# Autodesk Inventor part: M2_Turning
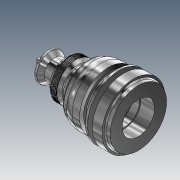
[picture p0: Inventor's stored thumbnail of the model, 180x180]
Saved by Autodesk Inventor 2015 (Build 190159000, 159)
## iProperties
Created: 2015-04
Part Number: M2_Turning
Material: Aço
Document SubType Name: Modeling
Designer: Andrew Almeida
Density: 7.85 g/cm^3
Appearance: Placa
Title: C:/Users/Andrew Almeida/Documents/Projeto WS2015/WS2015 CAD Data ANLAS/06/#06 - CNC Turning/01 - 3D Models/M2_Turning.stp
Creation Date: 2015-04-23
Sending System: Autodesk Translation Framework v4.0.0.5211
Preprocessor: ST-DEVELOPER v16.1
Author: Andrew Almeida
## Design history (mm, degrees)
node "M2_Turning1"
feature "Rosca1" dims "d0" = 10, "d1" = 0
feature "Rosca2" dims "d2" = 10, "d3" = 0
sketch "Esboço2"
  geometry: L1 (14.188, 0)-(14.188, 14.2); L2 (14.188, 14.2)-(13.447, 14.2); L3 (13.447, 14.2)-(13.447, 0); L4 (13.447, 0)-(14.188, 0); L5 (0, -49.8)-(0, 118.2) reference
  constraints: 8 end point
revolve "Revolução1" sketch "Esboço2" stored, may be unused: angle "d13" = 0 deg
sketch "Esboço1"
  geometry: L1 (-0.583, -0.051)-(-0.5, -0.051); L2 (0.083, -0.691)-(0, -0.851); L3 (-1, -0.851)-(-1.083, -0.691); L4 (-0.417, -0.051)-(-0.5, 0.109); L5 (-0.5, 0.109)-(-0.583, -0.051); L6 (-1, -0.851)-(-0.917, -0.691); L7 (-0.417, -0.051)-(-0.083, -0.691); L8 (-1.083, -0.691)-(-0.917, -0.691); L9 (0.083, -0.691)-(-0.083, -0.691); L10 (-1, -0.851)-(-1, -0.691); L11 (0, -0.851)-(0, -0.691); L12 (-0.5, 0.109)-(-0.5, 0); L13 (-1, -0.742)-(0, -0.742); L14 (-0.083, -0.691)-(0, -0.851); L15 (-0.917, -0.691)-(-0.583, -0.051); L16 (0, 0)-(0, 0.018); L17 (0, 0.018)-(0, 0); L18 (0, 0)-(0.033, 0); L19 (-0.5, 0)-(-0.5, -0.051); L20 (-0.5, -0.051)-(-0.417, -0.051); A1 r 0.094 centre (-1, -0.648) between (-1.083, -0.691) and (-1, -0.742); A2 r 0.094 centre (-1, -0.648) between (-1, -0.742) and (-0.917, -0.691); A3 r 0.094 centre (0, -0.648) between (-0.083, -0.691) and (0, -0.742); A4 r 0.094 centre (0, -0.648) between (0, -0.742) and (0.083, -0.691); A5 r 0.094 centre (-0.5, -0.094) between (-0.5, 0) and (-0.583, -0.051); A6 r 0.094 centre (-0.5, -0.094) between (-0.417, -0.051) and (-0.5, 0)
  constraints: 40 end point, 12 point on circle, 10 parallel, 8 tangent, 6 centre point, 6 collinear, 2 midpoint, 2 point on line, 1 horizontal, 1 perpendicular, 3 other
  dimensions: "d4" = 55 deg angle of L7 L15 (= d11); "d5" = 0.16008 distance of L4.end L1.end (= 0.160083 x Esboço1_Pitch); "d6" = 0.16008 distance of L2.end L11.end (= 0.160083 x Esboço1_Pitch); "Esboço1_ThreadOffset" = 0 distance between parallel lines of L16 L11; "Esboço1_MajorRadius" = 0.74146 distance from line of L13 L16.start; "d9" = 1 distance from line of L2.end L10 (= Esboço1_Pitch); "Esboço1_MinorRadius" = 0 distance edge to line of A6 L18 (derived)
feature "Espiral1" sketch "Esboço1" pitch "d14" = 1.5015; turns "d16" = 1; dims "d15" = 17.2, "d17" = 0, angle "d18" = 0 deg, angle "d19" = 0 deg, "d20" = 0, "d21" = 0
sketch "Esboço4"
  geometry: L1 (24, 0)-(24, 7.944); L2 (24, 7.944)-(23.259, 7.944); L3 (23.259, 7.944)-(23.259, 0); L4 (23.259, 0)-(24, 0); L5 (0, -101.056)-(0, 66.944) reference
  constraints: 8 end point
revolve "Revolução2" sketch "Esboço4" stored, may be unused: angle "d31" = 0 deg
sketch "Esboço5"
  geometry: L1 (24, 0)-(24, 7.944); L2 (24, 7.944)-(23.259, 7.944); L3 (23.259, 7.944)-(23.259, 0); L4 (23.259, 0)-(24, 0); L5 (0, -101.056)-(0, 66.944) reference
  constraints: 8 end point
revolve "Revolução3" sketch "Esboço5" stored, may be unused: angle "d32" = 0 deg
sketch "Esboço3"
  geometry: L1 (-0.583, -23.309)-(-0.5, -23.309); L2 (0.083, -23.95)-(0, -24.11); L3 (-1, -24.11)-(-1.083, -23.95); L4 (-0.417, -23.309)-(-0.5, -23.149); L5 (-0.5, -23.149)-(-0.583, -23.309); L6 (-1, -24.11)-(-0.917, -23.95); L7 (-0.417, -23.309)-(-0.083, -23.95); L8 (-1.083, -23.95)-(-0.917, -23.95); L9 (0.083, -23.95)-(-0.083, -23.95); L10 (-1, -24.11)-(-1, -23.95); L11 (0, -24.11)-(0, -23.95); L12 (-0.5, -23.149)-(-0.5, -23.259); L13 (-1, -24)-(0, -24); L14 (-0.083, -23.95)-(0, -24.11); L15 (-0.917, -23.95)-(-0.583, -23.309); L16 (0, 0)-(0, 0.018); L17 (0, 0.018)-(0, 0); L18 (0, 0)-(0.033, 0); L19 (-0.5, -23.259)-(-0.5, -23.309); L20 (-0.5, -23.309)-(-0.417, -23.309); A1 r 0.094 centre (-1, -23.906) between (-1.083, -23.95) and (-1, -24); A2 r 0.094 centre (-1, -23.906) between (-1, -24) and (-0.917, -23.95); A3 r 0.094 centre (0, -23.906) between (-0.083, -23.95) and (0, -24); A4 r 0.094 centre (0, -23.906) between (0, -24) and (0.083, -23.95); A5 r 0.094 centre (-0.5, -23.353) between (-0.5, -23.259) and (-0.583, -23.309); A6 r 0.094 centre (-0.5, -23.353) between (-0.417, -23.309) and (-0.5, -23.259)
  constraints: 40 end point, 12 point on circle, 10 parallel, 8 tangent, 6 centre point, 6 collinear, 2 midpoint, 2 point on line, 1 horizontal, 1 perpendicular, 3 other
  dimensions: "d22" = 55 deg angle of L7 L15 (= d29); "d23" = 0.16008 distance of L4.end L1.end (= 0.160083 x Esboço3_Pitch); "d24" = 0.16008 distance of L2.end L11.end (= 0.160083 x Esboço3_Pitch); "Esboço3_ThreadOffset" = 0 distance between parallel lines of L16 L11; "Esboço3_MajorRadius" = 24 distance from line of L13 L16.start; "d27" = 1 distance from line of L2.end L10 (= Esboço3_Pitch); "Esboço3_MinorRadius" = 23.25854 distance edge to line of A6 L18 (derived)
feature "Espiral2" sketch "Esboço3" pitch "d33" = 1.5015; turns "d35" = 1; dims "d34" = 10.9436, "d36" = 0, angle "d37" = 0 deg, angle "d38" = 0 deg, "d39" = 0, "d40" = 0
node "Body1"
node "Base1"
node "Sólido2"
node "Sólido3"
other parameters: "d11" = 55 deg [user parameter; used in 1 equation term], "Esboço1_Pitch" = 1 [user parameter; used in 3 equation terms], "d29" = 55 deg [user parameter; used in 1 equation term], "Esboço3_Pitch" = 1 [user parameter; used in 3 equation terms]
